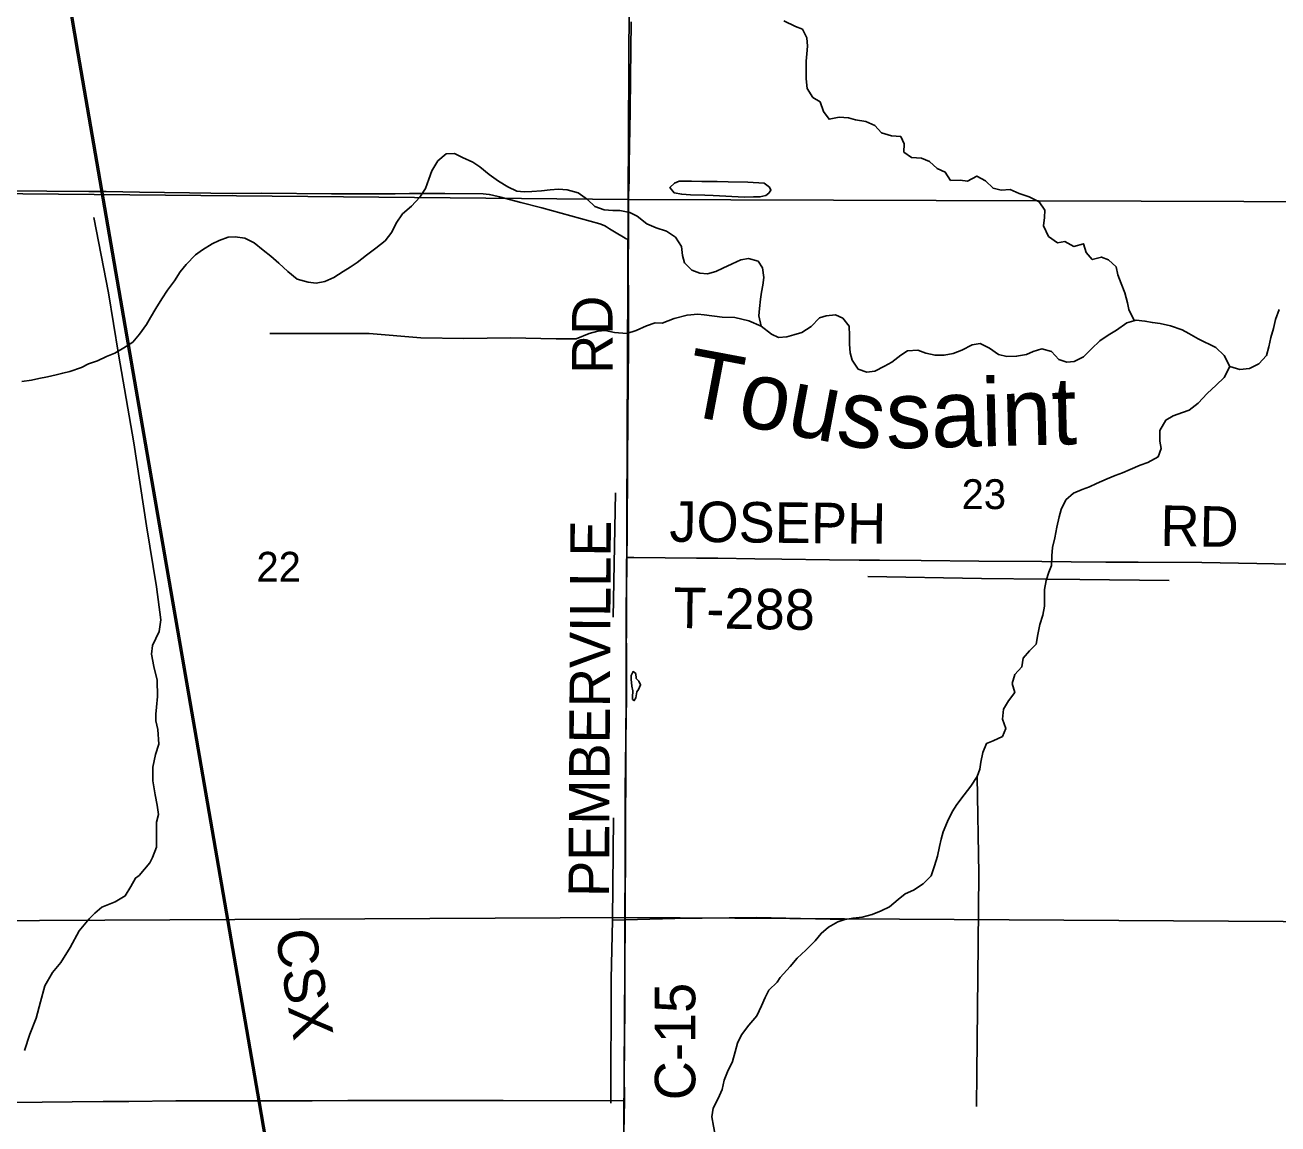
# Model space of a CAD drawing. Extents: x 0 to 34, y 0 to 22.
# Drawn here: x 4.664 to 6.42, y 17.765 to 19.306 of the extents above; entities that cross this region are included whole.
import ezdxf

# ---------------------------------------------------------------- set-up
doc = ezdxf.new("R2010")
doc.units = 0
for name, color, linetype in [('GM_X_County_Road', 7, 'Continuous'), ('GM_X_County_Road_Text', 7, 'Continuous'), ('GM_X_Major_River', 7, 'Continuous'), ('GM_X_Major_River_Text', 7, 'Continuous'), ('GM_X_Minor_Lake', 7, 'Continuous'), ('GM_X_Minor_River', 7, 'Continuous'), ('GM_X_Rail_Line', 7, 'Continuous'), ('GM_X_Rail_Line_Text', 7, 'Continuous'), ('GM_X_Section', 7, 'Continuous'), ('GM_X_Section_Text', 7, 'Continuous'), ('GM_X_State_Route', 7, 'Continuous'), ('GM_X_Township_Road', 7, 'Continuous'), ('GM_X_Township_Road_Text', 7, 'Continuous')]:
    doc.layers.add(name, color=color, linetype=linetype)

msp = doc.modelspace()

# ---------------------------------------------------------------- linework, layer by layer
at = {"layer": 'GM_X_County_Road'}
for points in [[(5.5098, 19.0051), (5.5097, 19.0476), (5.51, 19.0675), (5.5106, 19.0886), (5.5109, 19.111), (5.5114, 19.1359), (5.5119, 19.185), (5.5127, 19.2322), (5.5137, 19.3106)], [(5.5074, 18.5595), (5.5077, 18.591), (5.5081, 18.6264), (5.5083, 18.6569), (5.5086, 18.6901), (5.5089, 18.7565), (5.5091, 18.8044), (5.5096, 18.8579), (5.5098, 18.8958), (5.5098, 18.9232), (5.5095, 18.9598), (5.5095, 18.9779), (5.5098, 19.0051)], [(5.5041, 17.7977), (5.5039, 17.8368), (5.5043, 17.8697), (5.5042, 17.8859), (5.5045, 17.925), (5.5048, 17.9741), (5.5048, 18.0481), (5.5051, 18.1314), (5.505, 18.1625), (5.5052, 18.183), (5.5053, 18.1992), (5.5053, 18.2309), (5.5056, 18.2713), (5.5059, 18.303), (5.5069, 18.3642), (5.5069, 18.3897), (5.5067, 18.4892), (5.5073, 18.5458), (5.5074, 18.5595)], [(5.4967, 17.5463), (5.4988, 17.61), (5.4994, 17.6274), (5.5009, 17.6779), (5.5019, 17.7158), (5.5025, 17.7373), (5.503, 17.7535), (5.5041, 17.7977)]]:
    msp.add_lwpolyline(points, dxfattribs=at)
at = {"layer": 'GM_X_Major_River'}
for points in [[(5.3013, 19.1071), (5.2913, 19.1135), (5.277, 19.1203), (5.2658, 19.1258), (5.2541, 19.1254), (5.2425, 19.1154), (5.2342, 19.1016), (5.2297, 19.0899), (5.2252, 19.0767), (5.217, 19.0644), (5.2057, 19.0521), (5.1929, 19.0411), (5.1839, 19.028), (5.1779, 19.0156), (5.1685, 19.0033), (5.1557, 18.993), (5.1426, 18.9831), (5.1295, 18.9728), (5.1195, 18.9666), (5.1098, 18.9603), (5.0968, 18.9519), (5.0841, 18.9465), (5.072, 18.9442), (5.0606, 18.9456), (5.0452, 18.9498), (5.0322, 18.9603), (5.0196, 18.972), (5.0081, 18.9818), (4.9977, 18.9904), (4.9847, 19.0006), (4.972, 19.0073), (4.9584, 19.0092), (4.9486, 19.0083), (4.936, 19.004), (4.926, 18.9993), (4.9122, 18.9909), (4.9025, 18.9836), (4.8897, 18.9702), (4.8811, 18.9598), (4.8732, 18.9475), (4.8634, 18.9344), (4.8552, 18.9221), (4.8469, 18.9086), (4.8394, 18.8959), (4.8338, 18.8862), (4.824, 18.8724), (4.8146, 18.8612), (4.8023, 18.8532), (4.7896, 18.8459), (4.7778, 18.8412), (4.7651, 18.8351), (4.7525, 18.8309), (4.7426, 18.8258), (4.7266, 18.8201), (4.7164, 18.8179), (4.7071, 18.8153), (4.6953, 18.8129), (4.6831, 18.8105), (4.6728, 18.8081), (4.6591, 18.8062)], [(6.353, 18.827), (6.3449, 18.8424), (6.3334, 18.854), (6.3087, 18.866), (6.2957, 18.8736), (6.286, 18.8787), (6.2698, 18.8844), (6.2551, 18.8874), (6.2445, 18.8888), (6.234, 18.891), (6.2215, 18.8924), (6.2086, 18.8882), (6.1943, 18.8783), (6.1824, 18.871), (6.1708, 18.8633), (6.1588, 18.8518), (6.1479, 18.8407), (6.1349, 18.8342), (6.1243, 18.8333), (6.113, 18.837), (6.1027, 18.8483), (6.0895, 18.852), (6.0773, 18.8481), (6.0677, 18.8442), (6.054, 18.8415), (6.0404, 18.8414), (6.0288, 18.8442), (6.0161, 18.853), (6.003, 18.8594), (5.9916, 18.8574), (5.977, 18.8502), (5.9651, 18.8455), (5.9526, 18.8432), (5.9397, 18.8431), (5.9269, 18.8461), (5.9153, 18.8501), (5.9012, 18.8493), (5.8916, 18.8431), (5.8792, 18.8332), (5.8689, 18.8277), (5.8551, 18.8209), (5.844, 18.8195), (5.832, 18.8237), (5.8233, 18.8361), (5.8205, 18.8464), (5.8197, 18.8585), (5.8196, 18.8707), (5.8191, 18.8836), (5.8103, 18.8952), (5.8002, 18.8996), (5.7869, 18.8984), (5.7774, 18.8956), (5.7657, 18.8834), (5.7527, 18.875), (5.7416, 18.8718), (5.7317, 18.8686), (5.7203, 18.8678), (5.7103, 18.8727), (5.6957, 18.8839), (5.6926, 18.8984), (5.6933, 18.9083), (5.6947, 18.9215), (5.6961, 18.9314), (5.6982, 18.9412), (5.6997, 18.9521), (5.6977, 18.9655), (5.6915, 18.9751), (5.678, 18.9785), (5.6673, 18.9768), (5.6551, 18.9711), (5.642, 18.9653), (5.6321, 18.9602), (5.6206, 18.9571), (5.6097, 18.9581), (5.5984, 18.9624), (5.5885, 18.9727), (5.5853, 18.9826), (5.5841, 18.9955), (5.5757, 19.0083), (5.563, 19.0169), (5.5488, 19.0215), (5.5356, 19.0271), (5.5219, 19.038), (5.5118, 19.0432), (5.4975, 19.0458), (5.4878, 19.0461), (5.4755, 19.0468), (5.4624, 19.0516), (5.4521, 19.0614), (5.439, 19.0708), (5.4236, 19.075), (5.4115, 19.0756), (5.3997, 19.0748), (5.3876, 19.0736), (5.3743, 19.0727), (5.3637, 19.0722), (5.3531, 19.0732), (5.3404, 19.0789), (5.3273, 19.0872), (5.3143, 19.0962), (5.3013, 19.1071)], [(6.4222, 18.9073), (6.417, 18.893), (6.414, 18.8806), (6.4106, 18.8677)], [(6.4106, 18.8677), (6.4077, 18.8549), (6.4043, 18.8428), (6.3938, 18.831), (6.3804, 18.8244), (6.3671, 18.8232), (6.353, 18.827)]]:
    msp.add_lwpolyline(points, dxfattribs=at)
at = {"layer": 'GM_X_Minor_Lake'}
for p, q in [((5.6283, 19.067), (5.6725, 19.0648)), ((5.5146, 18.379), (5.516, 18.3725))]:
    msp.add_line(p, q, dxfattribs=at)
for points in [[(5.6725, 19.0648), (5.685, 19.0652), (5.6941, 19.065), (5.7025, 19.0671), (5.7064, 19.07), (5.7095, 19.0745), (5.7073, 19.0787), (5.6999, 19.0844), (5.6773, 19.0858), (5.6496, 19.0862), (5.634, 19.0866), (5.6127, 19.0866), (5.598, 19.087), (5.5807, 19.0871), (5.5742, 19.0842), (5.5679, 19.0783), (5.5736, 19.0707), (5.5844, 19.0688), (5.5966, 19.0681), (5.617, 19.0675), (5.6283, 19.067)], [(5.516, 18.3725), (5.5154, 18.3634), (5.5153, 18.3604), (5.5179, 18.3588), (5.5199, 18.3626), (5.5216, 18.3709), (5.524, 18.3742), (5.5268, 18.381), (5.5243, 18.386), (5.5206, 18.3899), (5.52, 18.3967), (5.5163, 18.3995), (5.5135, 18.3942), (5.5137, 18.3889), (5.5146, 18.379)]]:
    msp.add_lwpolyline(points, dxfattribs=at)
at = {"layer": 'GM_X_Minor_River'}
for points in [[(6.219, 18.8916), (6.2113, 18.9071), (6.2096, 18.9166), (6.2058, 18.9304), (6.2008, 18.9434), (6.1958, 18.9557), (6.1935, 18.9671), (6.1827, 18.9769), (6.173, 18.9805), (6.16, 18.977), (6.1516, 18.9871), (6.1477, 18.9993), (6.1343, 18.9955), (6.1216, 19.0023), (6.1114, 19.0006), (6.0987, 19.0096), (6.0919, 19.0246), (6.0933, 19.0363), (6.0936, 19.0462), (6.0855, 19.0582), (6.0717, 19.065), (6.0578, 19.0698), (6.0451, 19.0755), (6.0322, 19.0746), (6.0209, 19.0772), (6.0105, 19.0877), (5.9982, 19.0941), (5.9851, 19.0872), (5.975, 19.0885), (5.9613, 19.0881), (5.954, 19.0997), (5.9428, 19.1049), (5.9317, 19.1146), (5.9204, 19.1191), (5.9068, 19.1202), (5.896, 19.1277), (5.8963, 19.1394), (5.8916, 19.1498), (5.8784, 19.1508), (5.8645, 19.155), (5.8553, 19.1651), (5.8426, 19.1707), (5.8282, 19.1729), (5.8184, 19.1758), (5.8052, 19.1769), (5.7911, 19.1738), (5.7834, 19.1847), (5.7785, 19.1981), (5.7684, 19.2044), (5.7604, 19.2171), (5.7588, 19.2304), (5.7587, 19.2418), (5.7591, 19.2555), (5.7597, 19.2657), (5.7607, 19.2763), (5.7599, 19.2881), (5.7537, 19.3), (5.744, 19.304), (5.7275, 19.3116)], [(4.7945, 18.8446), (4.7804, 18.9304), (4.7599, 19.036)], [(5.6957, 18.8839), (5.6783, 18.8911), (5.6589, 18.8958), (5.6411, 18.8966), (5.6158, 18.8995), (5.6071, 18.9005), (5.5919, 18.8993), (5.5736, 18.8945), (5.5572, 18.888), (5.5474, 18.8883), (5.5351, 18.8844), (5.5206, 18.8779), (5.5076, 18.8737), (5.4902, 18.8749), (5.477, 18.8778), (5.4668, 18.8766), (5.4546, 18.8734), (5.4366, 18.8659), (5.4226, 18.8659), (5.4082, 18.8658), (5.3442, 18.8674), (5.2787, 18.8663), (5.2185, 18.8674), (5.1459, 18.8737), (5.0069, 18.8733)], [(4.7945, 18.8446), (4.8161, 18.72), (4.834, 18.6038), (4.8478, 18.5181), (4.8542, 18.472), (4.8515, 18.4558), (4.8423, 18.4359), (4.8409, 18.4238), (4.8443, 18.4066), (4.8487, 18.3875), (4.8493, 18.3644), (4.8478, 18.3496), (4.8468, 18.3398), (4.8469, 18.3306), (4.8496, 18.3181), (4.851, 18.2979), (4.8465, 18.2832), (4.843, 18.2655), (4.8429, 18.2465), (4.8462, 18.2267), (4.8489, 18.2122), (4.8505, 18.1992), (4.8479, 18.1883), (4.8479, 18.1724), (4.8478, 18.1534), (4.8425, 18.1387), (4.8386, 18.1316), (4.8234, 18.1138), (4.8183, 18.1101), (4.812, 18.0981), (4.8041, 18.085), (4.7899, 18.0766), (4.7711, 18.0691), (4.7615, 18.061), (4.7533, 18.0528), (4.7396, 18.0361), (4.7269, 18.0125), (4.7139, 17.9915), (4.7022, 17.9774), (4.6911, 17.9591), (4.6853, 17.9365), (4.679, 17.9138), (4.6701, 17.8913), (4.6628, 17.8683)], [(6.353, 18.827), (6.3449, 18.8116), (6.3336, 18.8009), (6.3212, 18.7894), (6.3088, 18.7757), (6.296, 18.7658), (6.2865, 18.7626), (6.2735, 18.758), (6.2633, 18.7521), (6.2548, 18.7375), (6.2548, 18.7227), (6.2568, 18.7121), (6.2524, 18.7008), (6.2378, 18.6928), (6.2271, 18.6889), (6.2133, 18.6828), (6.2026, 18.6781), (6.1923, 18.6745), (6.1812, 18.6695), (6.1662, 18.663), (6.1563, 18.6583), (6.146, 18.6548), (6.1337, 18.6498), (6.1229, 18.6402), (6.1165, 18.6267), (6.1136, 18.6165), (6.1106, 18.6021), (6.1075, 18.587), (6.1042, 18.5735), (6.1035, 18.5617), (6.1028, 18.5484), (6.0991, 18.5387), (6.0954, 18.527), (6.0932, 18.5145), (6.0929, 18.5012), (6.093, 18.4914), (6.0908, 18.4785), (6.0867, 18.4653), (6.0837, 18.4517), (6.0815, 18.4381), (6.0722, 18.4285), (6.0632, 18.4185), (6.0614, 18.406), (6.0516, 18.3952), (6.0479, 18.3828), (6.0514, 18.3702), (6.0424, 18.3583), (6.0357, 18.3466), (6.0342, 18.3326), (6.0388, 18.3196), (6.034, 18.3084), (6.0213, 18.3022), (6.0118, 18.2987), (6.0065, 18.2859), (6.0039, 18.2727), (6.0025, 18.2628), (5.9985, 18.2523), (5.9898, 18.2388), (5.9804, 18.2265), (5.9703, 18.2131), (5.9636, 18.2027), (5.9572, 18.1892), (5.9511, 18.1749), (5.9482, 18.1647), (5.9457, 18.1545), (5.9431, 18.1409), (5.939, 18.127), (5.9341, 18.1131), (5.9228, 18.1019), (5.9093, 18.0932), (5.8975, 18.0878), (5.8878, 18.08), (5.8758, 18.0697), (5.8643, 18.0639), (5.8513, 18.0589), (5.8376, 18.0554), (5.8247, 18.0538), (5.8133, 18.0518), (5.8033, 18.0487), (5.7903, 18.041), (5.7798, 18.0325), (5.7716, 18.0221), (5.7584, 18.0088), (5.7464, 17.9977), (5.7363, 17.9858), (5.7225, 17.9704), (5.7183, 17.9642), (5.7066, 17.9527), (5.7015, 17.9426), (5.6963, 17.931), (5.6895, 17.9171), (5.6785, 17.9037), (5.6684, 17.8903), (5.6624, 17.8787), (5.6594, 17.8666)], [(5.4883, 18.476), (5.4914, 18.6502)], [(6.2677, 18.527), (6.1428, 18.5285), (6.0951, 18.5289), (6.0046, 18.5299), (5.8456, 18.5327)], [(5.9985, 18.2523), (6.0008, 18.116), (5.9999, 18.0177), (5.998, 17.8364), (5.9976, 17.7897)], [(5.485, 17.7945), (5.4855, 17.9683), (5.4872, 18.051), (5.4888, 18.1944)], [(5.4872, 18.051), (5.5747, 18.0535), (5.6891, 18.0545), (5.8133, 18.0518)], [(5.6594, 17.8666), (5.6557, 17.853), (5.6485, 17.8384), (5.6437, 17.8267), (5.6411, 17.8135), (5.6355, 17.8011), (5.6287, 17.7873), (5.6265, 17.7752), (5.6288, 17.7622), (5.6309, 17.7523), (5.6317, 17.7401), (5.6291, 17.7277), (5.6205, 17.7169), (5.6119, 17.7057), (5.6036, 17.6907), (5.5972, 17.6787), (5.5842, 17.6714), (5.5728, 17.6702), (5.5587, 17.6679), (5.5488, 17.667), (5.5374, 17.6642), (5.5156, 17.656)]]:
    msp.add_lwpolyline(points, dxfattribs=at)
at = {"layer": 'GM_X_Rail_Line'}
for points in [[(5.5292, 14.4768), (5.5206, 14.546), (5.4959, 14.7503), (5.4725, 14.9371), (5.462, 15.0205), (5.4461, 15.156), (5.4028, 15.3982), (5.2961, 16.0228), (5.1204, 17.0387), (4.9909, 17.7947), (4.7368, 19.2661), (4.6073, 20.0278), (4.4575, 20.9)], [(5.5755, 14.1), (5.542, 14.3915), (5.5241, 14.5438), (5.4984, 14.7506), (5.475, 14.9374), (5.4645, 15.0208), (5.4485, 15.1564), (5.4052, 15.3987), (5.2986, 16.0233), (5.1228, 17.0391), (4.9933, 17.7951), (4.7392, 19.2665), (4.6097, 20.0282), (4.4576, 20.9)]]:
    msp.add_lwpolyline(points, dxfattribs=at)
at = {"layer": 'GM_X_Section'}
for points in [[(5.5144, 20.0832), (5.5091, 19.0615), (4.5106, 19.0706), (4.5187, 20.0828)], [(6.5307, 20.0674), (6.5168, 19.0579), (5.5091, 19.0615), (5.5144, 20.0832)], [(5.5091, 19.0615), (5.5052, 18.0545), (4.5012, 18.0497), (4.5106, 19.0706)], [(6.5168, 19.0579), (6.5049, 18.0487), (5.5052, 18.0545), (5.5091, 19.0615)], [(5.5052, 18.0545), (5.4985, 17.0434), (4.4954, 17.0428), (4.5012, 18.0497)], [(6.5049, 18.0487), (6.488, 17.04), (5.4985, 17.0434), (5.5052, 18.0545)]]:
    msp.add_lwpolyline(points, close=True, dxfattribs=at)
at = {"layer": 'GM_X_State_Route'}
for points in [[(4.4957, 17.7954), (4.4991, 17.7954), (4.519, 17.7951), (4.6455, 17.7954), (4.7296, 17.7964), (4.7731, 17.7969), (4.8092, 17.7969), (4.875, 17.7975), (4.9073, 17.7979), (4.9501, 17.7976), (4.9868, 17.7977), (5.0076, 17.7978), (5.066, 17.7979), (5.1163, 17.7981), (5.1723, 17.7982), (5.217, 17.7983), (5.3339, 17.7983), (5.5041, 17.7977)], [(5.5041, 17.7977), (5.503, 17.7535), (5.5025, 17.7373), (5.5019, 17.7158), (5.5009, 17.6779), (5.4994, 17.6274), (5.4988, 17.61), (5.4967, 17.5463)]]:
    msp.add_lwpolyline(points, dxfattribs=at)
at = {"layer": 'GM_X_Township_Road'}
for points in [[(4.594, 19.0733), (4.6941, 19.073), (4.7532, 19.0726), (4.7773, 19.0724), (4.8239, 19.0714), (4.8942, 19.0705), (4.9539, 19.0699), (4.9955, 19.07), (5.0932, 19.0694), (5.1827, 19.0695), (5.2026, 19.0696), (5.2524, 19.0696), (5.3058, 19.0692), (5.3104, 19.0689), (5.3145, 19.0684), (5.319, 19.0675), (5.3288, 19.0652), (5.3589, 19.0572), (5.3882, 19.0496), (5.4694, 19.027), (5.4731, 19.0256), (5.4764, 19.0242), (5.4789, 19.0228), (5.4831, 19.0203), (5.4879, 19.0175), (5.4926, 19.0144), (5.5028, 19.0084), (5.5052, 19.0071), (5.5066, 19.0064), (5.5098, 19.0051)], [(5.5074, 18.5595), (5.5171, 18.5594), (5.6053, 18.5585), (5.6352, 18.5584), (5.6868, 18.5577), (5.7246, 18.557), (5.7918, 18.5562), (5.8334, 18.5559), (5.8618, 18.5558), (5.9202, 18.5552), (6.001, 18.5543), (6.0893, 18.5536), (6.1304, 18.5532), (6.1789, 18.553), (6.2243, 18.5531), (6.3138, 18.5524), (6.3909, 18.5512), (6.513, 18.5485)]]:
    msp.add_lwpolyline(points, dxfattribs=at)

# ---------------------------------------------------------------- texts
at = {"layer": 'GM_X_County_Road_Text'}
for s, height, rotation, p in [('RD', 0.05682, 90, (5.4874, 18.8168)), ('PEMBERVILLE', 0.056818, 89.7019, (5.4824, 18.0834)), ('C-15', 0.05682, 90, (5.6035, 17.7985))]:
    msp.add_text(s, height=height, rotation=rotation, dxfattribs=at).set_placement(p)
at = {"layer": 'GM_X_Major_River_Text'}
for s, rotation, p in [('Tous', 349.313, (5.5837, 18.7605)), ('saint', 1.3128, (5.8716, 18.7121))]:
    msp.add_text(s, height=0.09475, rotation=rotation, dxfattribs=at).set_placement(p)
at = {"layer": 'GM_X_Rail_Line_Text'}
msp.add_text('CSX', height=0.05663, rotation=279.8998, dxfattribs=at).set_placement((5.0139, 18.0339))
at = {"layer": 'GM_X_Section_Text'}
for s, p in [('23', (5.9769, 18.6273)), ('22', (4.9881, 18.5255))]:
    msp.add_text(s, height=0.04186, rotation=0, dxfattribs=at).set_placement(p)
at = {"layer": 'GM_X_Township_Road_Text'}
for s, rotation, p in [('JOSEPH', 359.4222, (5.5669, 18.5816)), ('RD', 359.0109, (6.2552, 18.5758)), ('T-288', 359.1594, (5.5723, 18.4607))]:
    msp.add_text(s, height=0.05682, rotation=rotation, dxfattribs=at).set_placement(p)

doc.saveas('drawing.dxf')
